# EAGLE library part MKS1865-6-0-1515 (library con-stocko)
Serie MKS 1850 Lötstifte In-line, Raster 2.5 mm, Stiftwannen, stehend, mit Rastlasche Source: http://www.stocko.de/de/index.php?seite=ka_rfk2_mks1850.html&rubrik=Katalog+-+RFK+2 rfk_1850.pdf
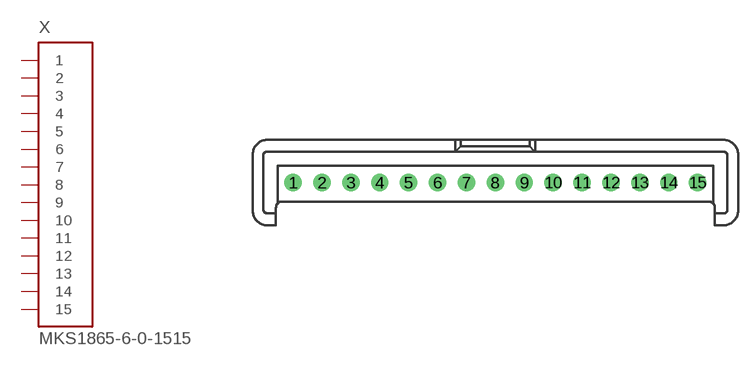
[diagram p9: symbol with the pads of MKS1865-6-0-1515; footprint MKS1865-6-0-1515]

Designator prefix X

## MKS1865-6-0-1515 (OC_FARNELL: unknown; OC_NEWARK: unknown)  [MKS1865-6-0-1515]
1  1  in
2  2  in
3  3  in
4  4  in
5  5  in
6  6  in
7  7  in
8  8  in
9  9  in
10  10  in
11  11  in
12  12  in
13  13  in
14  14  in
15  15  in

## Footprint MKS1865-6-0-1515 (pad centres in mm)
Serie MKS 1850 Lötstifte In-line, Raster 2.5 mm, Stiftwannen, stehend, mit Rastlasche Source: http://www.stocko.de/de/index.php?seite=ka_rfk2_mks1850.html&rubrik=Katalog+-+RFK+2 rfk_1850.pdf
drill 1 pad 1.422 round: 1 -17.5,0; 2 -15,0; 3 -12.5,0; 4 -10,0; 5 -7.5,0; 6 -5,0; 7 -2.5,0; 8 0,0; 9 2.5,0; 10 5,0; 11 7.5,0; 12 10,0; 13 12.5,0; 14 15,0; 15 17.5,0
